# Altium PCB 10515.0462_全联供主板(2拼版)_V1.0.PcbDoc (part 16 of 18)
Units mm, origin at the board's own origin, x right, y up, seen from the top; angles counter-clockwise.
Board outline 282 x 198 mm, 2 copper layers (Top Layer, Bottom Layer); 716 components, 0 nets, 2364 pads, 1800 vias.
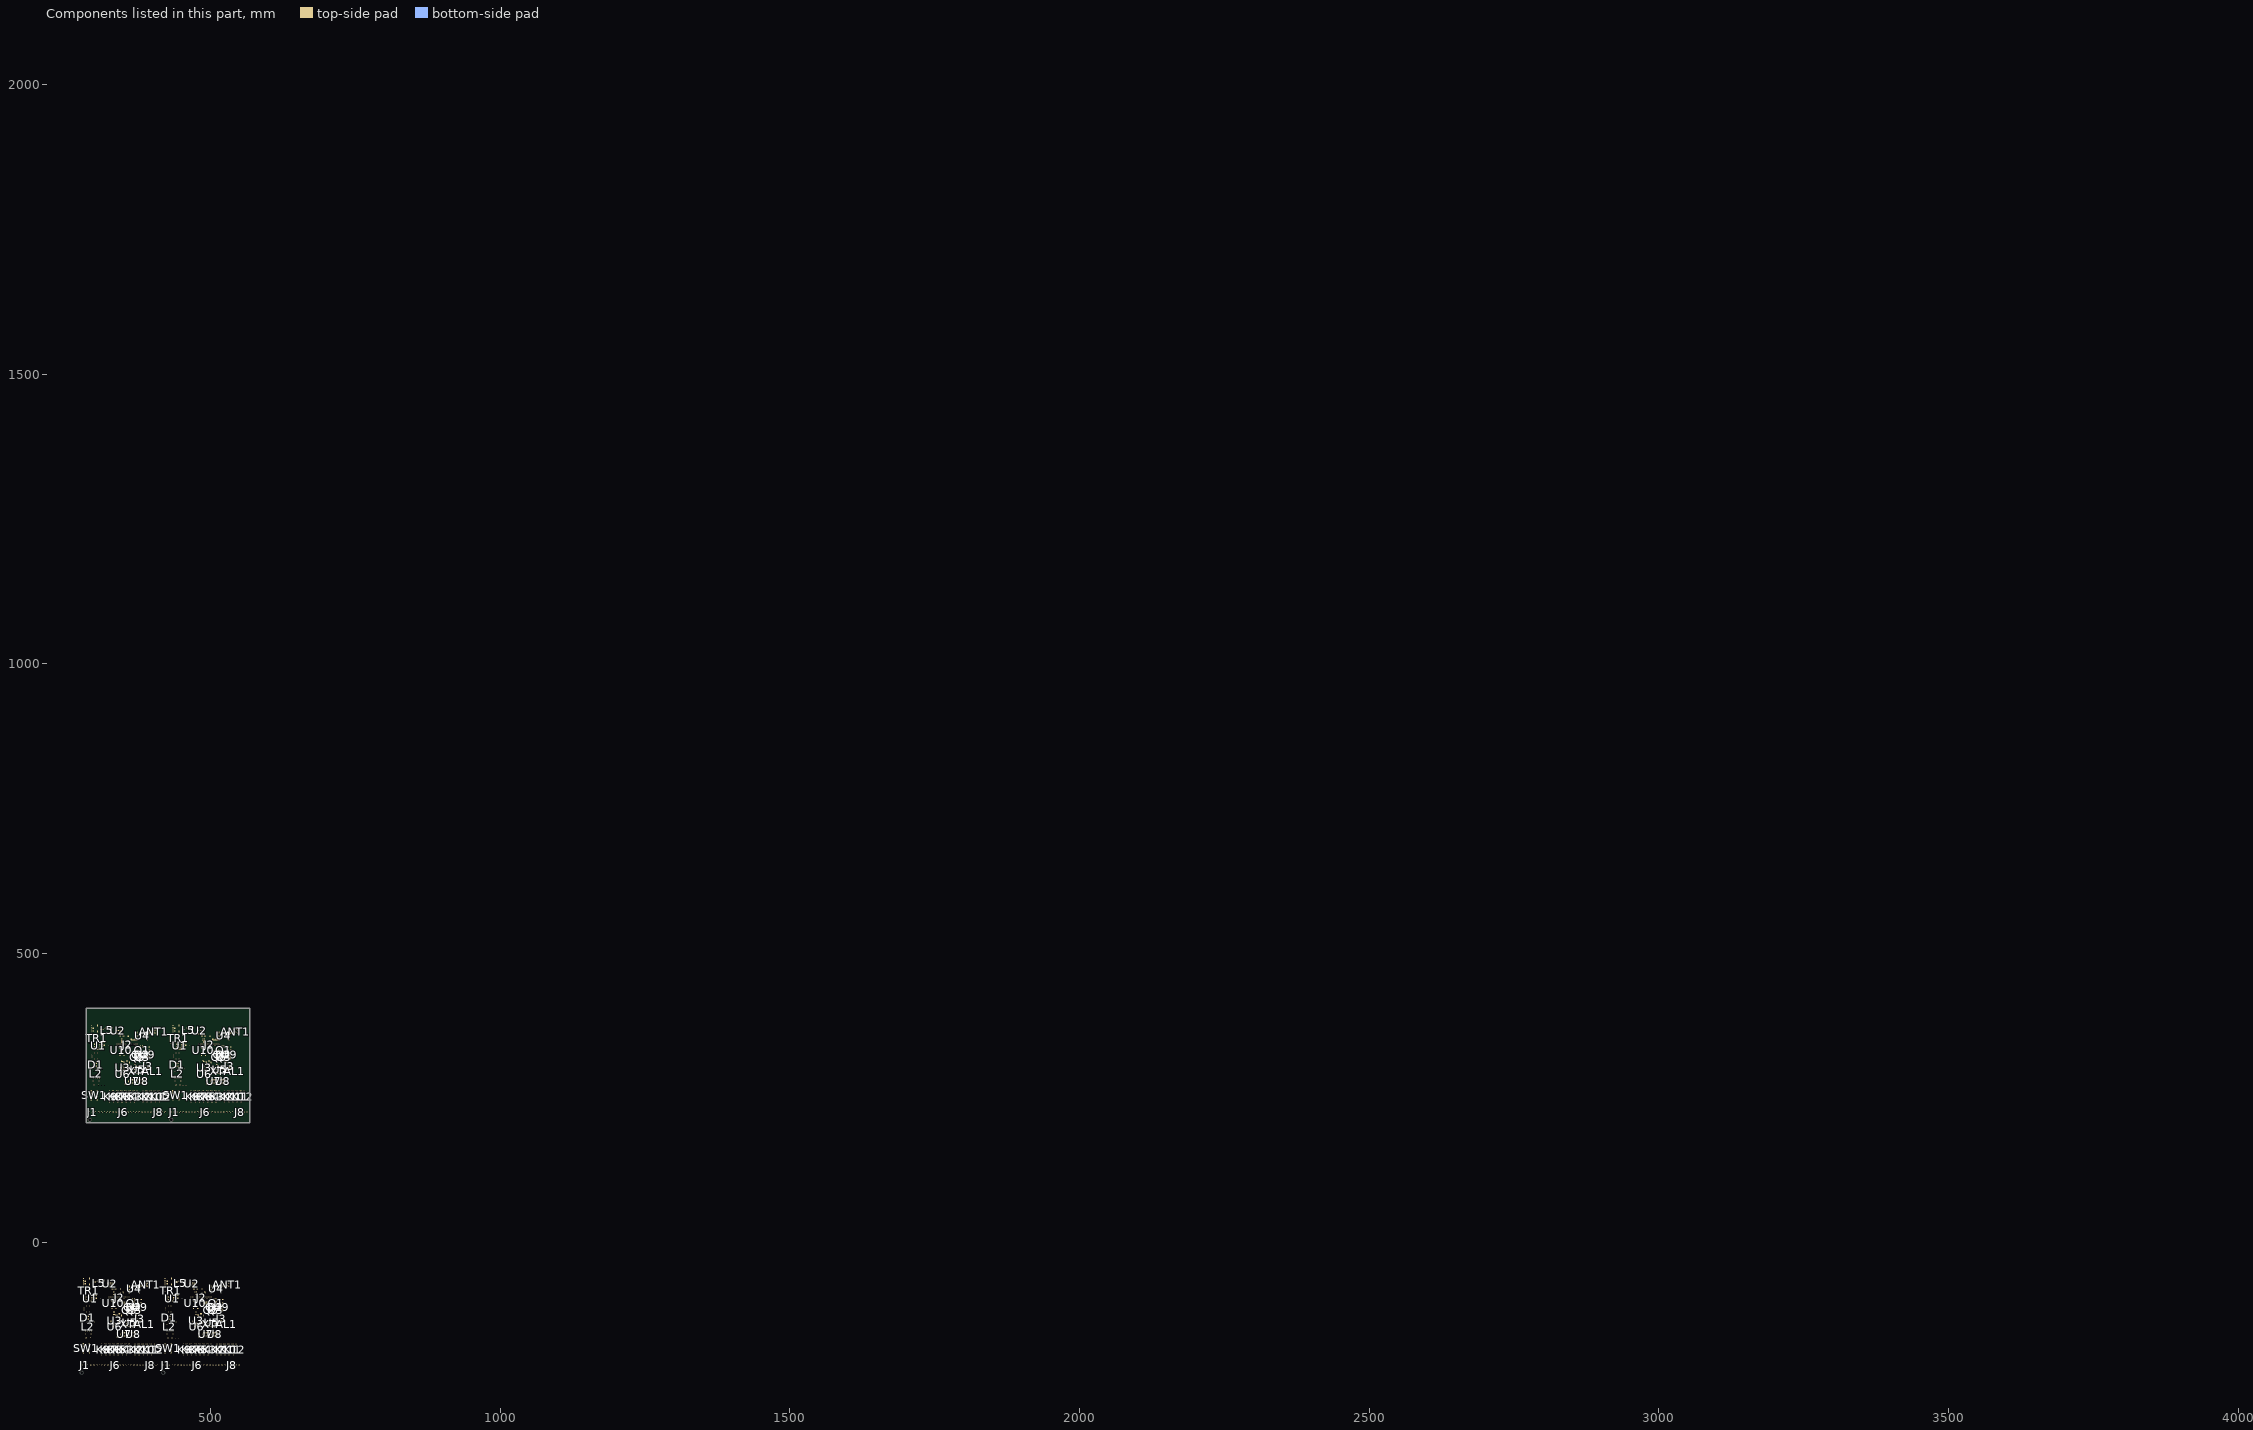
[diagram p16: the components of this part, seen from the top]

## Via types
v1: diameter 0.7, hole 0.4, Top Layer to Bottom Layer, tented both sides, 1800 vias

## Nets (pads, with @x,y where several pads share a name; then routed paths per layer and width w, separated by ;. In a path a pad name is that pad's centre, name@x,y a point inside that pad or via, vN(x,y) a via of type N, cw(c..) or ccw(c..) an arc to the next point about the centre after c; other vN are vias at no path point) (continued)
copper on no net: (continued)
  Bottom Layer w1.5: 278.999,-192.685 287.081,-200.767 287.081,-210.984 ; 278.999,-188.24 280.142,-189.383 280.142,-195.606 287.081,-202.545 ; 278.999,-187.478 278.237,-188.24 ; 280.015,-186.675 279.802,-186.675 278.237,-188.24 ; 280.142,-192.431 280.269,-192.431 287.889,-200.051 287.889,-210.592 287.497,-210.984 287.081,-210.984 ; 281.192,-115.353 283.317,-115.353 ; 281.192,-112.353 282.809,-112.353 ; v1(283.318,-126.457) 289.952,-126.487 ; 284.714,-93.244 283.605,-92.135 283.605,-89.826 285.677,-91.898 285.677,-103.531 285.677,-108.622 ; 284.714,-90.936 284.714,-107.087 285.677,-108.05 285.677,-108.622 ; 284.887,-116.924 cw(c283.101,-118.709) 285.627,-118.709 ; 285.094,-117.13 cw(c283.766,-118.457) 285.627,-118.703 ; 285.123,-110.04 ccw(c283.905,-108.822) 285.627,-108.822 ; 285.328,-107.701 cw(c284.607,-108.422) 285.627,-108.422 ; 285.677,-118.909 285.677,-116.409 284.621,-115.353 283.317,-115.353 ; 285.677,-117.628 285.592,-117.628 283.317,-115.353 ; 286.391,-200.077 286.391,-210.295 287.081,-210.984 ; 288.524,-126.487 288.524,-126.385 290.677,-124.232 ; 290.134,-176.175 291.912,-177.953 ; 290.175,-174.524 294.239,-174.524 295.382,-175.667 ; 290.261,-176.175 291.277,-177.191 ; 290.261,-175.921 294.747,-175.921 ; 290.302,-179.096 295.89,-179.096 ; 290.515,-177.191 293.985,-177.191 ; 290.642,-108.858 cw(c288.395,-111.104) 291.572,-111.104 ; 290.642,-108.387 ccw(c288.514,-106.26) 291.523,-106.26 ; 290.671,-108.373 ccw(c290.563,-107.419) 291.523,-107.419 ; 290.677,-119.66 291.826,-120.809 291.826,-124.613 289.952,-126.487 ; 290.727,-119.109 ccw(c292.177,-119.109) 291.152,-120.135 ; 290.727,-108.429 cw(c291.881,-108.583) 291.881,-107.419 291.523,-107.419 ; 290.82,-96.945 291.523,-96.243 ; 291.277,-177.953 303.383,-177.953 ; 291.572,-116.606 291.572,-109.518 292.334,-110.28 292.334,-117.252 290.677,-118.909 ; 292.605,-93.399 v1(289.059,-96.945) ; 292.605,-92.084 289.059,-95.63 v1(289.059,-96.945) ; 292.605,-89.826 292.605,-95.16 ; 292.628,243.91 300.71,235.829 300.71,225.611 ; 292.628,248.355 293.771,247.212 293.771,240.989 300.71,234.051 ; 292.628,249.117 291.866,248.355 ; 293.644,249.92 293.431,249.92 291.866,248.355 ; 293.705,-207.41 293.705,-210.24 292.961,-210.984 ; 293.771,244.164 293.898,244.164 301.518,236.544 301.518,226.003 301.125,225.611 300.71,225.611 ; 294.239,-175.921 295.382,-177.064 ; 294.477,-206.638 294.477,-204.86 ; 294.821,321.242 296.946,321.242 ; 294.821,324.242 296.438,324.242 ; 296.525,-204.59 292.961,-208.154 ; v1(296.947,310.139) 303.58,310.108 ; 297.961,-210.984 297.961,-208.394 311.671,-194.684 311.671,-193.252 ; 298.343,343.351 297.234,344.461 297.234,346.769 299.306,344.697 299.306,333.064 299.306,327.973 ; 298.343,345.66 298.343,329.508 299.306,328.546 299.306,327.973 ; 298.516,319.672 cw(c296.73,317.886) 299.256,317.886 ; 298.722,319.465 cw(c297.395,318.138) 299.256,317.893 ; 298.752,326.556 ccw(c297.534,327.773) 299.256,327.773 ; 298.957,328.894 cw(c298.236,328.173) 299.256,328.173 ; 299.306,317.686 299.306,320.186 298.25,321.242 296.946,321.242 ; 299.306,318.967 299.22,318.967 296.946,321.242 ; 300.02,236.518 300.02,226.301 300.71,225.611 ; 300.843,-79.528 302.05,-80.734 v1@303.129,-81.814 ; 300.843,-65.558 300.843,-80.925 ; 301.652,-197.685 301.652,-187.177 302.558,-186.271 ; 302.153,310.108 302.153,310.211 304.306,312.363 ; 302.211,-81.208 ccw(c303.675,-79.744) v1@303.675,-81.814 ; 302.338,-81.912 cw(c302.575,-82.149) 302.575,-81.814 ; 302.558,-195.225 303.447,-194.336 ; v1@302.667,-81.814 cw(c302.667,-82.149) v1@302.904,-81.912 ; 302.986,-196.351 302.558,-195.923 302.558,-186.271 ; 303.383,-178.588 303.383,-177.953 ; 303.453,-82.138 ccw(c303.637,-81.953) 303.637,-82.214 302.132,-82.214 300.843,-80.925 ; 303.763,260.42 305.541,258.642 ; 303.804,262.071 307.868,262.071 309.011,260.928 ; 303.89,260.42 304.906,259.404 ; 303.89,260.674 308.376,260.674 ; 303.931,257.499 309.519,257.499 ; v1@304.018,-81.814 301.732,-81.814 300.843,-80.925 ; 304.144,259.404 307.614,259.404 ; 304.27,327.738 cw(c302.024,325.491) 305.201,325.491 ; 304.27,328.208 ccw(c302.143,330.336) 305.152,330.336 ; 304.3,328.223 ccw(c304.191,329.177) 305.152,329.177 ; 304.306,316.935 305.455,315.786 305.455,311.982 303.58,310.108 ; 304.356,317.486 ccw(c305.806,317.486) 304.78,316.461 ; 304.355,328.166 cw(c305.51,328.012) 305.51,329.177 305.152,329.177 ; 304.449,339.65 305.152,340.353 ; 304.526,-179.096 301.605,-179.096 295.382,-179.096 ; 304.906,258.642 317.012,258.642 ; 305.201,319.99 305.201,327.078 305.963,326.316 305.963,319.343 304.306,317.686 ; 305.437,-194.209 305.128,-194.209 ; 305.437,-192.282 292.961,-204.758 ; 306.234,343.196 v1(302.688,339.65) ; 306.234,344.511 302.688,340.966 v1(302.688,339.65) ; 306.234,346.769 306.234,341.435 ; 306.241,-180.81 303.383,-177.953 ; 307.334,229.186 307.334,226.355 306.59,225.611 ; 307.868,260.674 309.011,259.531 ; 307.961,-210.984 307.961,-206.649 318.856,-195.754 318.856,-192.939 ; 308.105,229.957 308.105,231.735 ; 310.154,232.006 306.59,228.441 ; 311.59,225.611 311.59,228.201 325.3,241.911 325.3,243.343 ; 311.638,-185.7 312.4,-184.938 375.381,-184.938 376.568,-186.125 ; 311.671,-186.252 376.745,-186.252 376.789,-186.208 ; 311.777,-186.008 cw(c314.054,-188.285) 314.054,-185.065 ; 312.612,-185.065 cw(c312.612,-185.295) 312.806,-185.17 ; 314.472,357.067 315.678,355.861 v1@316.758,354.781 ; 314.472,371.037 314.472,355.67 ; 315.281,238.911 315.281,249.418 316.186,250.324 ; 315.84,355.388 ccw(c317.303,356.851) v1@317.303,354.781 ; 315.967,354.683 cw(c316.204,354.446) 316.204,354.781 ; 316.186,241.37 317.075,242.259 ; v1@316.296,354.781 cw(c316.296,354.446) v1@316.533,354.683 ; 316.371,-174.752 316.371,-172.331 317.469,-171.233 333.863,-171.233 ; 316.473,-185.065 cw(c316.473,-188.285) 318.75,-186.008 ; 316.614,240.244 316.186,240.672 316.186,250.324 ; 317.012,258.007 317.012,258.642 ; 317.082,354.458 ccw(c317.266,354.642) 317.266,354.381 315.761,354.381 314.472,355.67 ; v1@317.647,354.781 315.361,354.781 314.472,355.67 ; 317.961,-210.984 317.961,-204.65 326.016,-196.595 326.016,-192.939 ; 318.155,257.499 315.234,257.499 309.011,257.499 ; 318.848,-69.089 ccw(c319.303,-68.635) 319.303,-69.278 ; 318.959,-69.278 ccw(c318.959,-68.635) 319.414,-69.089 ; 318.962,-186.008 cw(c321.239,-188.285) 321.239,-185.065 ; 319.066,242.386 318.757,242.386 ; 319.066,244.313 306.59,231.837 ; 319.869,255.785 317.012,258.642 ; 320.176,-68.995 cw(c319.632,-69.539) 320.401,-69.539 ; 320.3,-92.762 320.3,-94.667 320.973,-95.339 ; 320.401,-92.863 320.401,-91.212 ; 320.401,-71.019 318.66,-69.278 320.311,-69.278 320.401,-69.368 320.401,-91.212 ; 320.438,-94.376 324.581,-94.376 ; 320.782,-93.752 323.692,-93.752 ccw(c323.692,-92.733) 324.571,-93.249 ; 321.125,-94.376 cw(c321.125,-99.251) 324.573,-95.804 ; 321.59,225.611 321.59,229.946 332.485,240.842 332.485,243.656 ; 321.847,-94.376 ccw(c321.847,-90.521) 324.573,-93.247 cw(c323.353,-92.028) 323.353,-93.752 ; 322.306,-93.117 320.401,-91.212 ; 323.386,-95.339 320.973,-95.339 ; 323.556,-174.752 323.556,-171.434 ; 323.633,-185.065 cw(c323.633,-188.285) 325.91,-186.008 ; 324.574,-95.786 ccw(c322.733,-93.256) 325.862,-93.256 ccw(c329.024,-93.256) 327.128,-95.786 ; 324.573,-93.265 cw(c322.342,-95.987) 325.862,-95.987 ; 324.581,-93.382 324.581,-95.795 ; 324.581,-93.255 325.862,-93.255 ; 325.267,250.895 326.029,251.657 389.01,251.657 390.197,250.47 ; 325.3,250.343 390.374,250.343 390.418,250.387 ; 325.406,250.587 cw(c327.683,248.311) 327.683,251.53 ; 325.862,-95.977 cw(c329.4,-95.977) 327.129,-93.265 ; 325.862,-95.668 325.862,-93.255 ; 326.122,-186.008 cw(c328.399,-188.285) 328.399,-185.065 ; 326.241,251.53 cw(c326.241,251.3) 326.434,251.425 ; 327.961,-210.984 327.961,-204.937 333.175,-199.723 333.175,-193.066 ; 330,261.843 330,264.264 331.097,265.362 347.492,265.362 ; 330.102,251.53 cw(c330.102,248.311) 332.379,250.587 ; 330.716,-174.752 330.716,-171.24 ; 330.793,-185.065 cw(c330.793,-188.285) 333.069,-186.008 ; 331.59,225.611 331.59,231.945 339.645,240 339.645,243.656 ; 332.466,-171.233 333.863,-169.836 333.863,-169.698 ; 332.477,367.506 ccw(c332.932,367.961) 332.932,367.318 ; 332.588,367.318 ccw(c332.588,367.961) 333.043,367.506 ; 332.591,250.587 cw(c334.868,248.311) 334.868,251.53 ; 333.282,-186.008 cw(c335.558,-188.285) 335.558,-185.065 ; 333.805,367.601 cw(c333.261,367.057) 334.03,367.057 ; 333.863,-170.333 333.863,-159.284 v1@333.99,-159.157 ; 333.929,343.834 333.929,341.929 334.601,341.256 ; 334.03,343.732 334.03,345.383 ; 334.03,365.576 332.289,367.318 333.94,367.318 334.03,367.227 334.03,345.383 ; 334.067,342.22 338.21,342.22 ; 334.411,342.843 337.321,342.843 ccw(c337.321,343.863) 338.199,343.346 ; 334.754,342.22 cw(c334.754,337.344) 338.201,340.792 ; 335.26,-171.233 335.26,-171.095 333.863,-169.698 ; 335.476,342.22 ccw(c335.476,346.074) 338.201,343.349 cw(c336.982,344.568) 336.982,342.843 ; 335.935,343.478 334.03,345.383 ; 337.014,341.256 334.601,341.256 ; 337.185,261.843 337.185,265.162 ; 337.262,251.53 cw(c337.262,248.311) 339.539,250.587 ; 337.875,-174.752 337.875,-171.402 ; 337.952,-185.065 cw(c337.952,-188.285) 340.229,-186.008 ; 337.961,-210.984 337.961,-203.7 340.34,-201.321 340.34,-193.066 ; 338.203,340.81 ccw(c336.362,343.34) 339.491,343.34 ccw(c342.652,343.34) 340.757,340.81 ; 338.202,343.331 cw(c335.971,340.608) 339.491,340.608 ; 338.21,343.213 338.21,340.8 ; 338.21,343.34 339.491,343.34 ; 339.491,340.619 cw(c343.028,340.619) 340.757,343.331 ; 339.491,340.927 339.491,343.34 ; 339.751,250.587 cw(c342.027,248.311) 342.027,251.53 ; 340.335,-193.252 340.34,-193.257 ; 340.441,-186.008 cw(c342.718,-188.285) 342.718,-185.065 ; 341.59,225.611 341.59,231.658 346.804,236.873 346.804,243.529 ; 344.345,261.843 344.345,265.356 ; 344.421,251.53 cw(c344.421,248.311) 346.698,250.587 ; 345.035,-174.752 345.035,-171.271 ; 345.112,-185.065 cw(c345.112,-188.285) 347.389,-186.008 ; 346.095,265.362 347.492,266.759 347.492,266.897 ; 346.91,250.587 cw(c349.187,248.311) 349.187,251.53 ; 347.492,266.262 347.492,277.311 v1@347.619,277.438 ; 347.495,-192.939 347.495,-210.518 347.961,-210.984 ; 347.601,-186.008 cw(c349.878,-188.285) 349.878,-185.065 ; 348.889,265.362 348.889,265.5 347.492,266.897 ; 351.504,261.843 351.504,265.194 ; 351.581,251.53 cw(c351.581,248.311) 353.858,250.587 ; 351.59,225.611 351.59,232.895 353.969,235.274 353.969,243.529 ; 352.195,-174.752 352.195,-171.37 ; 352.214,-185.065 cw(c352.214,-188.285) 354.491,-186.008 ; 353.964,243.343 353.969,243.338 ; 354.07,250.587 cw(c356.347,248.311) 356.347,251.53 ; 354.597,-193.066 354.597,-203.513 357.961,-206.877 357.961,-210.984 ; 354.703,-186.008 cw(c356.98,-188.285) 356.98,-185.065 ; 358.664,261.843 358.664,265.324 ; 358.741,251.53 cw(c358.741,248.311) 361.017,250.587 ; 359.297,-174.752 359.297,-171.487 ; 361.124,243.656 361.124,226.077 361.59,225.611 ; 361.23,250.587 cw(c363.506,248.311) 363.506,251.53 ; 365.823,261.843 365.823,265.225 ; 365.843,251.53 cw(c365.843,248.311) 368.12,250.587 ; 367.38,-185.065 cw(c367.38,-187.851) 369.35,-185.881 ; 367.961,-210.984 367.961,-194.02 369.296,-192.685 ; 367.961,-194.62 369.456,-193.125 ; 368.226,243.529 368.226,233.083 371.59,229.719 371.59,225.611 ; 368.28,-195.352 369.456,-194.176 369.456,-192.812 ; 368.332,250.587 cw(c370.609,248.311) 370.609,251.53 ; 369.562,-185.881 cw(c371.532,-187.851) 371.532,-185.065 ; 372.926,261.843 372.926,265.108 ; 374.156,-174.625 374.156,-171.487 ; 374.492,-185.065 cw(c374.492,-187.851) 376.462,-185.881 ; 375.508,-185.065 cw(c375.508,-185.998) 376.421,-185.806 ; 375.714,-185.271 ccw(c376.568,-184.418) 376.568,-185.625 ; 376.568,-192.812 376.568,-201.989 378.059,-203.48 378.059,-210.886 377.961,-210.984 ; 381.009,251.53 cw(c381.009,248.744) 382.979,250.714 ; 381.268,-174.625 381.268,-171.233 ; 381.59,225.611 381.59,242.575 382.925,243.91 ; 381.59,241.975 383.085,243.47 ; 381.909,241.243 383.085,242.419 383.085,243.783 ; 383.191,250.714 cw(c385.161,248.744) 385.161,251.53 ; 387.785,261.97 387.785,265.108 ; 388.121,251.53 cw(c388.121,248.744) 390.091,250.714 ; 388.387,-174.625 388.387,-171.24 ; 389.137,251.53 cw(c389.137,250.597) 390.05,250.79 ; 389.343,251.324 ccw(c390.197,252.178) 390.197,250.97 ; 390.197,243.783 390.197,234.607 391.688,233.115 391.688,225.709 391.59,225.611 ; 394.897,261.97 394.897,265.362 ; 395.499,-174.625 395.499,-171.494 395.238,-171.233 ; 402.016,261.97 402.016,265.355 ; 402.738,-174.625 402.738,-172.129 401.842,-171.233 395.238,-171.233 ; 409.128,261.97 409.128,265.101 408.867,265.362 ; 416.367,261.97 416.367,264.466 415.471,265.362 408.867,265.362 ; 419.999,-192.685 428.081,-200.767 428.081,-210.984 ; 419.999,-188.24 421.142,-189.383 421.142,-195.606 428.081,-202.545 ; 419.999,-187.478 419.237,-188.24 ; 421.015,-186.675 420.802,-186.675 419.237,-188.24 ; 421.142,-192.431 421.269,-192.431 428.889,-200.051 428.889,-210.592 428.497,-210.984 428.081,-210.984 ; 422.192,-115.353 424.317,-115.353 ; 422.192,-112.353 423.809,-112.353 ; v1(424.318,-126.457) 430.952,-126.487 ; 425.714,-93.244 424.605,-92.135 424.605,-89.826 426.677,-91.898 426.677,-103.531 426.677,-108.622 ; 425.714,-90.936 425.714,-107.087 426.677,-108.05 426.677,-108.622 ; 425.887,-116.924 cw(c424.101,-118.709) 426.627,-118.709 ; 426.094,-117.13 cw(c424.766,-118.457) 426.627,-118.703 ; 426.123,-110.04 ccw(c424.905,-108.822) 426.627,-108.822 ; 426.328,-107.701 cw(c425.607,-108.422) 426.627,-108.422 ; 426.677,-118.909 426.677,-116.409 425.621,-115.353 424.317,-115.353 ; 426.677,-117.628 426.592,-117.628 424.317,-115.353 ; 427.391,-200.077 427.391,-210.295 428.081,-210.984 ; 429.524,-126.487 429.524,-126.385 431.677,-124.232 ; 431.134,-176.175 432.912,-177.953 ; 431.175,-174.524 435.239,-174.524 436.382,-175.667 ; 431.261,-176.175 432.277,-177.191 ; 431.261,-175.921 435.747,-175.921 ; 431.302,-179.096 436.89,-179.096 ; 431.515,-177.191 434.985,-177.191 ; 431.642,-108.858 cw(c429.395,-111.104) 432.572,-111.104 ; 431.642,-108.387 ccw(c429.514,-106.26) 432.523,-106.26 ; 431.671,-108.373 ccw(c431.563,-107.419) 432.523,-107.419 ; 431.677,-119.66 432.826,-120.809 432.826,-124.613 430.952,-126.487 ; 431.727,-108.429 cw(c432.881,-108.583) 432.881,-107.419 432.523,-107.419 ; 431.727,-119.109 ccw(c433.177,-119.109) 432.152,-120.135 ; 431.82,-96.945 432.523,-96.243 ; 432.277,-177.953 444.383,-177.953 ; 432.572,-116.606 432.572,-109.518 433.334,-110.28 433.334,-117.252 431.677,-118.909 ; 433.605,-93.399 v1(430.059,-96.945) ; 433.605,-92.084 430.059,-95.63 v1(430.059,-96.945) ; 433.605,-89.826 433.605,-95.16 ; 433.628,243.91 441.71,235.829 441.71,225.611 ; 433.628,248.355 434.771,247.212 434.771,240.989 441.71,234.051 ; 433.628,249.117 432.866,248.355 ; 434.644,249.92 434.431,249.92 432.866,248.355 ; 434.705,-207.41 434.705,-210.24 433.961,-210.984 ; 434.771,244.164 434.898,244.164 442.518,236.544 442.518,226.003 442.125,225.611 441.71,225.611 ; 435.239,-175.921 436.382,-177.064 ; 435.477,-206.638 435.477,-204.86 ; 435.821,321.242 437.946,321.242 ; 435.821,324.242 437.438,324.242 ; 437.525,-204.59 433.961,-208.154 ; v1(437.947,310.139) 444.58,310.108 ; 438.961,-210.984 438.961,-208.394 452.671,-194.684 452.671,-193.252 ; 439.343,343.351 438.234,344.461 438.234,346.769 440.306,344.697 440.306,333.064 440.306,327.973 ; 439.343,345.66 439.343,329.508 440.306,328.546 440.306,327.973 ; 439.516,319.672 cw(c437.73,317.886) 440.256,317.886 ; 439.722,319.465 cw(c438.395,318.138) 440.256,317.893 ; 439.752,326.556 ccw(c438.534,327.773) 440.256,327.773 ; 439.957,328.894 cw(c439.236,328.173) 440.256,328.173 ; 440.306,317.686 440.306,320.186 439.25,321.242 437.946,321.242 ; 440.306,318.967 440.22,318.967 437.946,321.242 ; 441.02,236.518 441.02,226.301 441.71,225.611 ; 441.843,-79.528 443.05,-80.734 v1@444.129,-81.814 ; 441.843,-65.558 441.843,-80.925 ; 442.652,-197.685 442.652,-187.177 443.558,-186.271 ; 443.153,310.108 443.153,310.211 445.306,312.363 ; 443.211,-81.208 ccw(c444.675,-79.744) v1@444.675,-81.814 ; 443.338,-81.912 cw(c443.575,-82.149) 443.575,-81.814 ; 443.558,-195.225 444.447,-194.336 ; v1@443.667,-81.814 cw(c443.667,-82.149) v1@443.904,-81.912 ; 443.986,-196.351 443.558,-195.923 443.558,-186.271 ; 444.383,-178.588 444.383,-177.953 ; 444.453,-82.138 ccw(c444.637,-81.953) 444.637,-82.214 443.132,-82.214 441.843,-80.925 ; 444.763,260.42 446.541,258.642 ; 444.804,262.071 448.868,262.071 450.011,260.928 ; 444.89,260.42 445.906,259.404 ; 444.89,260.674 449.376,260.674 ; 444.931,257.499 450.519,257.499 ; v1@445.018,-81.814 442.732,-81.814 441.843,-80.925 ; 445.144,259.404 448.614,259.404 ; 445.27,327.738 cw(c443.024,325.491) 446.201,325.491 ; 445.27,328.208 ccw(c443.143,330.336) 446.152,330.336 ; 445.3,328.223 ccw(c445.191,329.177) 446.152,329.177 ; 445.306,316.935 446.455,315.786 446.455,311.982 444.58,310.108 ; 445.355,328.166 cw(c446.51,328.012) 446.51,329.177 446.152,329.177 ; 445.356,317.486 ccw(c446.806,317.486) 445.78,316.461 ; 445.449,339.65 446.152,340.353 ; 445.526,-179.096 442.605,-179.096 436.382,-179.096 ; 445.906,258.642 458.012,258.642 ; 446.201,319.99 446.201,327.078 446.963,326.316 446.963,319.343 445.306,317.686 ; 446.437,-194.209 446.128,-194.209 ; 446.437,-192.282 433.961,-204.758 ; 447.234,343.196 v1(443.688,339.65) ; 447.234,344.511 443.688,340.966 v1(443.688,339.65) ; 447.234,346.769 447.234,341.435 ; 447.241,-180.81 444.383,-177.953 ; 448.334,229.186 448.334,226.355 447.59,225.611 ; 448.868,260.674 450.011,259.531 ; 448.961,-210.984 448.961,-206.649 459.856,-195.754 459.856,-192.939 ; 449.105,229.957 449.105,231.735 ; 451.154,232.006 447.59,228.441 ; 452.59,225.611 452.59,228.201 466.3,241.911 466.3,243.343 ; 452.638,-185.7 453.4,-184.938 516.381,-184.938 517.568,-186.125 ; 452.671,-186.252 517.745,-186.252 517.789,-186.208 ; 452.777,-186.008 cw(c455.054,-188.285) 455.054,-185.065 ; 453.612,-185.065 cw(c453.612,-185.295) 453.806,-185.17 ; 455.472,357.067 456.678,355.861 v1@457.758,354.781 ; 455.472,371.037 455.472,355.67 ; 456.281,238.911 456.281,249.418 457.186,250.324 ; 456.84,355.388 ccw(c458.303,356.851) v1@458.303,354.781 ; 456.967,354.683 cw(c457.204,354.446) 457.204,354.781 ; 457.186,241.37 458.075,242.259 ; v1@457.296,354.781 cw(c457.296,354.446) v1@457.533,354.683 ; 457.371,-174.752 457.371,-172.331 458.469,-171.233 474.863,-171.233 ; 457.473,-185.065 cw(c457.473,-188.285) 459.75,-186.008 ; 457.614,240.244 457.186,240.672 457.186,250.324 ; 458.012,258.007 458.012,258.642 ; 458.082,354.458 ccw(c458.266,354.642) 458.266,354.381 456.761,354.381 455.472,355.67 ; v1@458.647,354.781 456.361,354.781 455.472,355.67 ; 458.961,-210.984 458.961,-204.65 467.016,-196.595 467.016,-192.939 ; 459.155,257.499 456.234,257.499 450.011,257.499 ; 459.848,-69.089 ccw(c460.303,-68.635) 460.303,-69.278 ; 459.959,-69.278 ccw(c459.959,-68.635) 460.414,-69.089 ; 459.962,-186.008 cw(c462.239,-188.285) 462.239,-185.065 ; 460.066,242.386 459.757,242.386 ; 460.066,244.313 447.59,231.837 ; 460.869,255.785 458.012,258.642 ; 461.176,-68.995 cw(c460.632,-69.539) 461.401,-69.539 ; 461.3,-92.762 461.3,-94.667 461.973,-95.339 ; 461.401,-92.863 461.401,-91.212 ; 461.401,-71.019 459.66,-69.278 461.311,-69.278 461.401,-69.368 461.401,-91.212 ; 461.438,-94.376 465.581,-94.376 ; 461.782,-93.752 464.692,-93.752 ccw(c464.692,-92.733) 465.571,-93.249 ; 462.125,-94.376 cw(c462.125,-99.251) 465.573,-95.804 ; 462.59,225.611 462.59,229.946 473.485,240.842 473.485,243.656 ; 462.847,-94.376 ccw(c462.847,-90.521) 465.573,-93.247 cw(c464.353,-92.028) 464.353,-93.752 ; 463.306,-93.117 461.401,-91.212 ; 464.386,-95.339 461.973,-95.339 ; 464.556,-174.752 464.556,-171.434 ; 464.633,-185.065 cw(c464.633,-188.285) 466.91,-186.008 ; 465.573,-93.265 cw(c463.342,-95.987) 466.862,-95.987 ; 465.574,-95.786 ccw(c463.733,-93.256) 466.862,-93.256 ccw(c470.024,-93.256) 468.128,-95.786 ; 465.581,-93.382 465.581,-95.795 ; 465.581,-93.255 466.862,-93.255 ; 466.267,250.895 467.029,251.657 530.01,251.657 531.197,250.47 ; 466.3,250.343 531.374,250.343 531.418,250.387 ; 466.406,250.587 cw(c468.683,248.311) 468.683,251.53 ; 466.862,-95.977 cw(c470.4,-95.977) 468.129,-93.265 ; 466.862,-95.668 466.862,-93.255 ; 467.122,-186.008 cw(c469.399,-188.285) 469.399,-185.065 ; 467.241,251.53 cw(c467.241,251.3) 467.434,251.425 ; 468.961,-210.984 468.961,-204.937 474.175,-199.723 474.175,-193.066 ; 471,261.843 471,264.264 472.097,265.362 488.492,265.362 ; 471.102,251.53 cw(c471.102,248.311) 473.379,250.587 ; 471.716,-174.752 471.716,-171.24 ; 471.793,-185.065 cw(c471.793,-188.285) 474.069,-186.008 ; 472.59,225.611 472.59,231.945 480.645,240 480.645,243.656 ; 473.466,-171.233 474.863,-169.836 474.863,-169.698 ; 473.477,367.506 ccw(c473.932,367.961) 473.932,367.318 ; 473.588,367.318 ccw(c473.588,367.961) 474.043,367.506 ; 473.591,250.587 cw(c475.868,248.311) 475.868,251.53 ; 474.282,-186.008 cw(c476.558,-188.285) 476.558,-185.065 ; 474.805,367.601 cw(c474.261,367.057) 475.03,367.057 ; 474.863,-170.333 474.863,-159.284 v1@474.99,-159.157 ; 474.929,343.834 474.929,341.929 475.601,341.256 ; 475.03,343.732 475.03,345.383 ; 475.03,365.576 473.289,367.318 474.94,367.318 475.03,367.227 475.03,345.383 ; 475.067,342.22 479.21,342.22 ; 475.411,342.843 478.321,342.843 ccw(c478.321,343.863) 479.199,343.346 ; 475.754,342.22 cw(c475.754,337.344) 479.201,340.792 ; 476.26,-171.233 476.26,-171.095 474.863,-169.698 ; 476.476,342.22 ccw(c476.476,346.074) 479.201,343.349 cw(c477.982,344.568) 477.982,342.843 ; 476.935,343.478 475.03,345.383 ; 478.014,341.256 475.601,341.256 ; 478.185,261.843 478.185,265.162 ; 478.262,251.53 cw(c478.262,248.311) 480.539,250.587 ; 478.875,-174.752 478.875,-171.402 ; 478.952,-185.065 cw(c478.952,-188.285) 481.229,-186.008 ; 478.961,-210.984 478.961,-203.7 481.34,-201.321 481.34,-193.066 ; 479.203,340.81 ccw(c477.362,343.34) 480.491,343.34 ccw(c483.652,343.34) 481.757,340.81 ; 479.202,343.331 cw(c476.971,340.608) 480.491,340.608 ; 479.21,343.213 479.21,340.8 ; 479.21,343.34 480.491,343.34 ; 480.491,340.619 cw(c484.028,340.619) 481.757,343.331 ; 480.491,340.927 480.491,343.34 ; 480.751,250.587 cw(c483.027,248.311) 483.027,251.53 ; 481.335,-193.252 481.34,-193.257 ; 481.441,-186.008 cw(c483.718,-188.285) 483.718,-185.065 ; 482.59,225.611 482.59,231.658 487.804,236.873 487.804,243.529 ; 485.345,261.843 485.345,265.356 ; 485.421,251.53 cw(c485.421,248.311) 487.698,250.587 ; 486.035,-174.752 486.035,-171.271 ; 486.112,-185.065 cw(c486.112,-188.285) 488.389,-186.008 ; 487.095,265.362 488.492,266.759 488.492,266.897 ; 487.91,250.587 cw(c490.187,248.311) 490.187,251.53 ; 488.492,266.262 488.492,277.311 v1@488.619,277.438 ; 488.495,-192.939 488.495,-210.518 488.961,-210.984 ; 488.601,-186.008 cw(c490.878,-188.285) 490.878,-185.065 ; 489.889,265.362 489.889,265.5 488.492,266.897 ; 492.504,261.843 492.504,265.194 ; 492.581,251.53 cw(c492.581,248.311) 494.858,250.587 ; 492.59,225.611 492.59,232.895 494.969,235.274 494.969,243.529 ; 493.195,-174.752 493.195,-171.37 ; 493.214,-185.065 cw(c493.214,-188.285) 495.491,-186.008 ; 494.964,243.343 494.969,243.338 ; 495.07,250.587 cw(c497.347,248.311) 497.347,251.53 ; 495.597,-193.066 495.597,-203.513 498.961,-206.877 498.961,-210.984 ; 495.703,-186.008 cw(c497.98,-188.285) 497.98,-185.065 ; 499.664,261.843 499.664,265.324 ; 499.741,251.53 cw(c499.741,248.311) 502.017,250.587 ; 500.297,-174.752 500.297,-171.487 ; 502.124,243.656 502.124,226.077 502.59,225.611 ; 502.23,250.587 cw(c504.506,248.311) 504.506,251.53 ; 506.824,261.843 506.824,265.225 ; 506.843,251.53 cw(c506.843,248.311) 509.12,250.587 ; 508.38,-185.065 cw(c508.38,-187.851) 510.35,-185.881 ; 508.961,-210.984 508.961,-194.02 510.296,-192.685 ; 508.961,-194.62 510.456,-193.125 ; 509.226,243.529 509.226,233.083 512.59,229.719 512.59,225.611 ; 509.28,-195.352 510.456,-194.176 510.456,-192.812 ; 509.332,250.587 cw(c511.609,248.311) 511.609,251.53 ; 510.562,-185.881 cw(c512.532,-187.851) 512.532,-185.065 ; 513.926,261.843 513.926,265.108 ; 515.156,-174.625 515.156,-171.487 ; 515.492,-185.065 cw(c515.492,-187.851) 517.462,-185.881 ; 516.508,-185.065 cw(c516.508,-185.998) 517.421,-185.806 ; 516.714,-185.271 ccw(c517.568,-184.418) 517.568,-185.625 ; 517.568,-192.812 517.568,-201.989 519.059,-203.48 519.059,-210.886 518.961,-210.984 ; 522.009,251.53 cw(c522.009,248.744) 523.979,250.714 ; 522.268,-174.625 522.268,-171.233 ; 522.59,225.611 522.59,242.575 523.925,243.91 ; 522.59,241.975 524.085,243.47 ; 522.909,241.243 524.085,242.419 524.085,243.783 ; 524.191,250.714 cw(c526.161,248.744) 526.161,251.53 ; 528.785,261.97 528.785,265.108 ; 529.121,251.53 cw(c529.121,248.744) 531.091,250.714 ; 529.387,-174.625 529.387,-171.24 ; 530.137,251.53 cw(c530.137,250.597) 531.05,250.79 ; 530.343,251.324 ccw(c531.197,252.178) 531.197,250.97 ; 531.197,243.783 531.197,234.607 532.688,233.115 532.688,225.709 532.59,225.611 ; 535.897,261.97 535.897,265.362 ; 536.499,-174.625 536.499,-171.494 536.238,-171.233 ; 543.016,261.97 543.016,265.355 ; 543.738,-174.625 543.738,-172.129 542.842,-171.233 536.238,-171.233 ; 550.128,261.97 550.128,265.101 549.867,265.362 ; 557.367,261.97 557.367,264.466 556.471,265.362 549.867,265.362 ; 278.237,-188.24 278.237,-195.352 278.999,-196.114 ; 278.237,-188.24 278.237,-187.437 278.999,-186.675 278.999,-196.114 ; 278.999,-196.114 287.081,-204.196 287.081,-210.984 ; 282.809,-112.353 285.677,-109.486 285.677,-108.622 ; 282.809,-112.353 284.446,-112.353 285.677,-111.122 285.677,-108.622 ; v1(289.059,-96.945) 290.677,-98.563 290.677,-108.622 ; v1(289.059,-96.945) 290.677,-96.945 290.677,-108.622 ; 289.952,-126.487 290.677,-125.762 290.677,-124.232 ; 290.677,-124.232 290.677,-118.909 ; 290.677,-118.909 290.677,-108.622 ; 290.677,-108.622 292.605,-106.694 292.605,-95.16 ; 291.523,-107.419 291.523,-96.243 ; 291.523,-96.243 292.605,-95.16 ; 291.866,248.355 291.866,241.243 292.628,240.481 ; 291.866,248.355 291.866,249.158 292.628,249.92 292.628,240.481 ; 292.628,240.481 300.71,232.4 300.71,225.611 ; 292.961,-210.984 292.961,-206.376 ; 292.961,-210.984 292.961,-208.154 ; 292.961,-208.154 305.437,-195.678 306.304,-194.811 306.304,-184.049 ; 292.961,-206.376 292.961,-204.758 ; 292.961,-206.376 294.477,-204.86 ; 292.961,-204.758 292.961,-203.361 301.986,-194.336 303.447,-194.336 ; 293.985,-177.191 302.621,-177.191 303.383,-177.953 ; 293.985,-177.191 295.382,-178.588 295.382,-179.096 ; 294.477,-204.86 305.128,-194.209 ; 295.382,-179.096 295.382,-177.064 ; 295.382,-177.064 295.382,-175.667 ; 295.382,-175.667 296.525,-176.81 303.637,-176.81 ; 296.438,324.242 299.306,327.11 299.306,327.973 ; 296.438,324.242 298.075,324.242 299.306,325.473 299.306,327.973 ; 302.558,-186.271 303.447,-185.382 ; v1(302.688,339.65) 304.306,338.032 304.306,327.973 ; v1(302.688,339.65) 304.306,339.65 304.306,327.973 ; 303.447,-194.336 303.447,-185.382 ; 303.447,-194.336 304.018,-193.764 304.018,-184.811 ; 303.447,-185.382 304.018,-184.811 ; 303.58,310.108 304.306,310.833 304.306,312.363 ; 303.637,-176.81 306.304,-179.477 306.304,-184.049 ; 303.637,-176.81 305.034,-176.81 ; 304.018,-184.811 305.034,-183.795 ; 304.306,312.363 304.306,317.686 ; 304.306,317.686 304.306,327.973 ; 304.306,327.973 306.234,329.901 306.234,341.435 ; 305.034,-183.795 306.304,-182.525 306.453,-182.376 306.453,-178.229 ; 305.034,-183.795 305.034,-194.115 305.128,-194.209 ; 305.034,-176.81 306.453,-178.229 ; 305.034,-176.81 306.812,-176.81 308.336,-178.334 308.336,-182.017 306.304,-184.049 ; 305.152,329.177 305.152,340.353 ; 305.152,340.353 306.234,341.435 ; 306.304,-184.049 306.304,-182.906 307.574,-181.636 307.574,-179.35 306.453,-178.229 ; 306.59,225.611 306.59,230.219 ; 306.59,225.611 306.59,228.441 ; 306.59,228.441 319.066,240.918 319.933,241.785 319.933,252.546 ; 306.59,230.219 306.59,231.837 ; 306.59,230.219 308.105,231.735 ; 306.59,231.837 306.59,233.234 315.615,242.259 317.075,242.259 ; 307.614,259.404 316.25,259.404 317.012,258.642 ; 307.614,259.404 309.011,258.007 309.011,257.499 ; 308.105,231.735 318.757,242.386 ; 309.011,257.499 309.011,259.531 ; 309.011,259.531 309.011,260.928 ; 309.011,260.928 310.154,259.785 317.266,259.785 ; 316.186,250.324 317.075,251.213 ; 317.075,242.259 317.075,251.213 ; 317.075,242.259 317.647,242.831 317.647,251.784 ; 317.075,251.213 317.647,251.784 ; 317.266,259.785 319.933,257.118 319.933,252.546 ; 317.266,259.785 318.663,259.785 ; 317.647,251.784 318.663,252.8 ; 318.663,252.8 319.933,254.07 320.082,254.219 320.082,258.366 ; 318.663,252.8 318.663,242.48 318.757,242.386 ; 318.663,259.785 320.082,258.366 ; 318.663,259.785 320.441,259.785 321.965,258.261 321.965,254.578 319.933,252.546 ; 319.933,252.546 319.933,253.689 321.203,254.959 321.203,257.245 320.082,258.366 ; 320.973,-95.339 321.429,-95.795 324.581,-95.795 ; 324.573,-95.804 ccw(c323.451,-96.925) 323.451,-95.339 cw(c323.451,-96.925) 324.573,-95.804 ; 324.581,-95.795 327.121,-95.795 327.121,-93.255 325.862,-93.255 ; 333.863,-171.233 333.863,-169.698 ; 333.863,-171.233 381.268,-171.233 ; 334.601,341.256 335.057,340.8 338.21,340.8 ; 338.201,340.792 ccw(c337.08,339.67) 337.08,341.256 cw(c337.08,339.67) 338.201,340.792 ; 338.21,340.8 340.75,340.8 340.75,343.34 339.491,343.34 ; 347.492,265.362 347.492,266.897 ; 347.492,265.362 394.897,265.362 ; 381.268,-171.233 395.238,-171.233 ; 394.897,265.362 408.867,265.362 ; 419.237,-188.24 419.237,-195.352 419.999,-196.114 ; 419.237,-188.24 419.237,-187.437 419.999,-186.675 419.999,-196.114 ; 419.999,-196.114 428.081,-204.196 428.081,-210.984 ; 423.809,-112.353 426.677,-109.486 426.677,-108.622 ; 423.809,-112.353 425.446,-112.353 426.677,-111.122 426.677,-108.622 ; v1(430.059,-96.945) 431.677,-98.563 431.677,-108.622 ; v1(430.059,-96.945) 431.677,-96.945 431.677,-108.622 ; 430.952,-126.487 431.677,-125.762 431.677,-124.232 ; 431.677,-124.232 431.677,-118.909 ; 431.677,-118.909 431.677,-108.622 ; 431.677,-108.622 433.605,-106.694 433.605,-95.16 ; 432.523,-107.419 432.523,-96.243 ; 432.523,-96.243 433.605,-95.16 ; 432.866,248.355 432.866,241.243 433.628,240.481 ; 432.866,248.355 432.866,249.158 433.628,249.92 433.628,240.481 ; 433.628,240.481 441.71,232.4 441.71,225.611 ; 433.961,-210.984 433.961,-206.376 ; 433.961,-210.984 433.961,-208.154 ; 433.961,-208.154 446.437,-195.678 447.304,-194.811 447.304,-184.049 ; 433.961,-206.376 433.961,-204.758 ; 433.961,-206.376 435.477,-204.86 ; 433.961,-204.758 433.961,-203.361 442.986,-194.336 444.447,-194.336 ; 434.985,-177.191 443.621,-177.191 444.383,-177.953 ; 434.985,-177.191 436.382,-178.588 436.382,-179.096 ; 435.477,-204.86 446.128,-194.209 ; 436.382,-179.096 436.382,-177.064 ; 436.382,-177.064 436.382,-175.667 ; 436.382,-175.667 437.525,-176.81 444.637,-176.81 ; 437.438,324.242 440.306,327.11 440.306,327.973 ; 437.438,324.242 439.075,324.242 440.306,325.473 440.306,327.973 ; 443.558,-186.271 444.447,-185.382 ; v1(443.688,339.65) 445.306,338.032 445.306,327.973 ; v1(443.688,339.65) 445.306,339.65 445.306,327.973 ; 444.447,-194.336 444.447,-185.382 ; 444.447,-194.336 445.018,-193.764 445.018,-184.811 ; 444.447,-185.382 445.018,-184.811 ; 444.58,310.108 445.306,310.833 445.306,312.363 ; 444.637,-176.81 447.304,-179.477 447.304,-184.049 ; 444.637,-176.81 446.034,-176.81 ; 445.018,-184.811 446.034,-183.795 ; 445.306,312.363 445.306,317.686 ; 445.306,317.686 445.306,327.973 ; 445.306,327.973 447.234,329.901 447.234,341.435 ; 446.034,-183.795 447.304,-182.525 447.453,-182.376 447.453,-178.229 ; 446.034,-183.795 446.034,-194.115 446.128,-194.209 ; 446.034,-176.81 447.453,-178.229 ; 446.034,-176.81 447.812,-176.81 449.336,-178.334 449.336,-182.017 447.304,-184.049 ; 446.152,329.177 446.152,340.353 ; 446.152,340.353 447.234,341.435 ; 447.304,-184.049 447.304,-182.906 448.574,-181.636 448.574,-179.35 447.453,-178.229 ; 447.59,225.611 447.59,230.219 ; 447.59,225.611 447.59,228.441 ; 447.59,228.441 460.066,240.918 460.933,241.785 460.933,252.546 ; 447.59,230.219 447.59,231.837 ; 447.59,230.219 449.105,231.735 ; 447.59,231.837 447.59,233.234 456.615,242.259 458.075,242.259 ; 448.614,259.404 457.25,259.404 458.012,258.642 ; 448.614,259.404 450.011,258.007 450.011,257.499 ; 449.105,231.735 459.757,242.386 ; 450.011,257.499 450.011,259.531 ; 450.011,259.531 450.011,260.928 ; 450.011,260.928 451.154,259.785 458.266,259.785 ; 457.186,250.324 458.075,251.213 ; 458.075,242.259 458.075,251.213 ; 458.075,242.259 458.647,242.831 458.647,251.784 ; 458.075,251.213 458.647,251.784 ; 458.266,259.785 460.933,257.118 460.933,252.546 ; 458.266,259.785 459.663,259.785 ; 458.647,251.784 459.663,252.8 ; 459.663,252.8 460.933,254.07 461.082,254.219 461.082,258.366 ; 459.663,252.8 459.663,242.48 459.757,242.386 ; 459.663,259.785 461.082,258.366 ; 459.663,259.785 461.441,259.785 462.965,258.261 462.965,254.578 460.933,252.546 ; 460.933,252.546 460.933,253.689 462.203,254.959 462.203,257.245 461.082,258.366 ; 461.973,-95.339 462.429,-95.795 465.581,-95.795 ; 465.573,-95.804 ccw(c464.451,-96.925) 464.451,-95.339 cw(c464.451,-96.925) 465.573,-95.804 ; 465.581,-95.795 468.121,-95.795 468.121,-93.255 466.862,-93.255 ; 474.863,-171.233 474.863,-169.698 ; 474.863,-171.233 522.268,-171.233 ; 475.601,341.256 476.057,340.8 479.21,340.8 ; 479.201,340.792 ccw(c478.08,339.67) 478.08,341.256 cw(c478.08,339.67) 479.201,340.792 ; 479.21,340.8 481.75,340.8 481.75,343.34 480.491,343.34 ; 488.492,265.362 488.492,266.897 ; 488.492,265.362 535.897,265.362 ; 522.268,-171.233 536.238,-171.233 ; 535.897,265.362 549.867,265.362
  Bottom Layer w2: 277.081,-223.787 277.081,-210.984 ; 290.71,212.809 290.71,225.611 ; 418.081,-223.787 418.081,-210.984 ; 431.71,212.809 431.71,225.611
